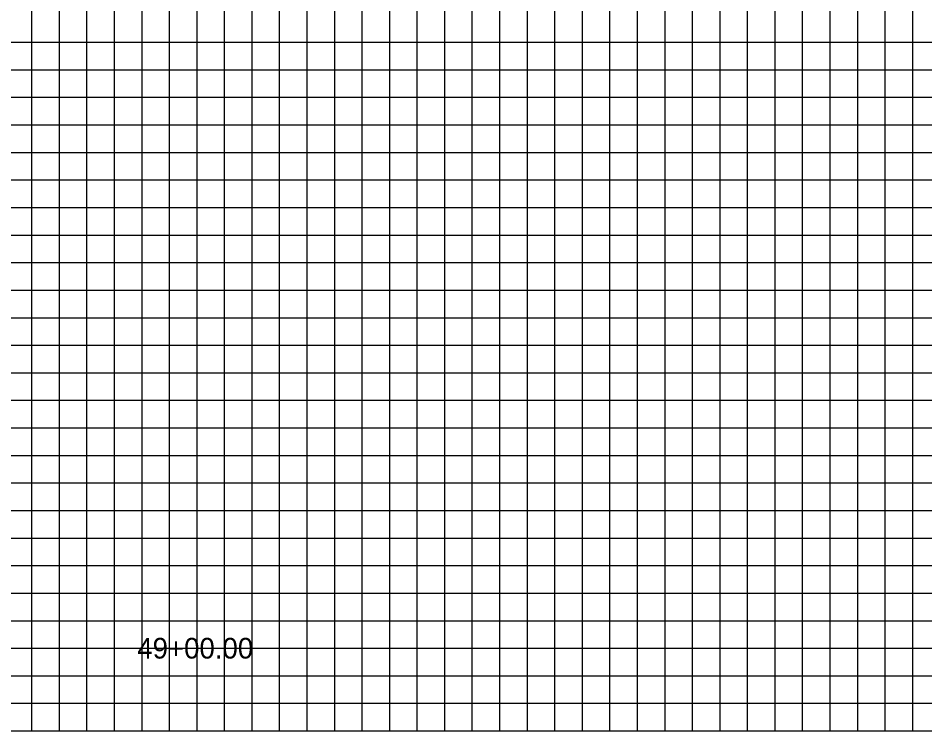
# Model space of a CAD drawing. Extents: x 967 to 1623, y 964 to 7064.
# Drawn here: x 1147 to 1212.9, y 4920 to 4971.7 of the extents above; entities that cross this region are included whole.
import ezdxf

# ---------------------------------------------------------------- set-up
doc = ezdxf.new("R2010")
doc.units = 0
for name, color, linetype in [('Default', 7, 'Continuous'), ('RD_SHT_MjGrid', 7, 'Continuous'), ('RD_SHT_MnGrid', 7, 'Continuous')]:
    doc.layers.add(name, color=color, linetype=linetype)

msp = doc.modelspace()

# ---------------------------------------------------------------- linework, layer by layer
at = {"layer": 'RD_SHT_MjGrid'}
for p, q in [((1150, 4920), (1150, 5090)), ((1160, 4920), (1160, 5090)), ((1170, 4920), (1170, 5090)), ((1180, 4920), (1180, 5090)), ((1190, 4920), (1190, 5090)), ((1200, 4920), (1200, 5090)), ((1210, 4920), (1210, 5090)), ((1000, 4970), (1320, 4970)), ((1000, 4960), (1320, 4960)), ((1000, 4950), (1320, 4950)), ((1000, 4940), (1320, 4940)), ((1000, 4930), (1320, 4930)), ((1000, 4920), (1320, 4920))]:
    msp.add_line(p, q, dxfattribs=at)
at = {"layer": 'RD_SHT_MnGrid'}
for p, q in [((1148, 4920), (1148, 5090)), ((1152, 4920), (1152, 5090)), ((1154, 4920), (1154, 5090)), ((1156, 4920), (1156, 5090)), ((1158, 4920), (1158, 5090)), ((1162, 4920), (1162, 5090)), ((1164, 4920), (1164, 5090)), ((1166, 4920), (1166, 5090)), ((1168, 4920), (1168, 5090)), ((1172, 4920), (1172, 5090)), ((1174, 4920), (1174, 5090)), ((1176, 4920), (1176, 5090)), ((1178, 4920), (1178, 5090)), ((1182, 4920), (1182, 5090)), ((1184, 4920), (1184, 5090)), ((1186, 4920), (1186, 5090)), ((1188, 4920), (1188, 5090)), ((1192, 4920), (1192, 5090)), ((1194, 4920), (1194, 5090)), ((1196, 4920), (1196, 5090)), ((1198, 4920), (1198, 5090)), ((1202, 4920), (1202, 5090)), ((1204, 4920), (1204, 5090)), ((1206, 4920), (1206, 5090)), ((1208, 4920), (1208, 5090)), ((1212, 4920), (1212, 5090)), ((1000, 4968), (1320, 4968)), ((1000, 4966), (1320, 4966)), ((1000, 4964), (1320, 4964)), ((1000, 4962), (1320, 4962)), ((1000, 4958), (1320, 4958)), ((1000, 4956), (1320, 4956)), ((1000, 4954), (1320, 4954)), ((1000, 4952), (1320, 4952)), ((1000, 4948), (1320, 4948)), ((1000, 4946), (1320, 4946)), ((1000, 4944), (1320, 4944)), ((1000, 4942), (1320, 4942)), ((1000, 4938), (1320, 4938)), ((1000, 4936), (1320, 4936)), ((1000, 4934), (1320, 4934)), ((1000, 4932), (1320, 4932)), ((1000, 4928), (1320, 4928)), ((1000, 4926), (1320, 4926)), ((1000, 4924), (1320, 4924)), ((1000, 4922), (1320, 4922))]:
    msp.add_line(p, q, dxfattribs=at)

# ---------------------------------------------------------------- texts
at = {"layer": 'Default'}
msp.add_text('49+00.00', height=1.5, dxfattribs=at).set_placement((1155.656, 4925.249))

doc.saveas('drawing.dxf')
